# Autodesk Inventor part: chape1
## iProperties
Created: 2009-03
Part Number: chape1
Document SubType Name: Modeling
Designer: Ordi1
Author: Ordi1
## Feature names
1. Extrusion2
2. Perçage1 [Hole]
3. Chanfrein1 [Chamfer]
